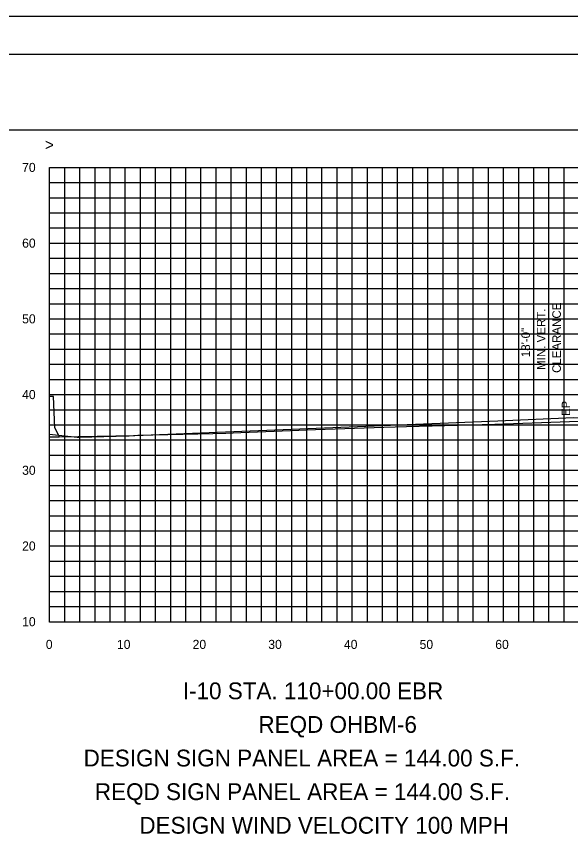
# Model space of a CAD drawing. Extents: x 1797809 to 2198143, y 249608 to 1237864.
# Drawn here: x 2195038.5 to 2195111.7, y 1237228.8 to 1237338 of the extents above; entities that cross this region are included whole.
import ezdxf

# ---------------------------------------------------------------- set-up
doc = ezdxf.new("R2010")
doc.units = 0
for name, color, linetype in [('10', 7, 'Continuous'), ('31', 7, 'Continuous'), ('60', 7, 'Continuous'), ('Default', 7, 'Continuous'), ('DESIGN - SHEET - Light Grid', 7, 'Continuous'), ('DESIGN - TRAFFIC CONTROL PERMANENT - Signs', 7, 'Continuous'), ('GSCOLORFILL', 7, 'Continuous'), ('GSSHT', 7, 'Continuous'), ('Level 45', 7, 'Continuous'), ('Level 55', 7, 'Continuous')]:
    doc.layers.add(name, color=color, linetype=linetype)

msp = doc.modelspace()

# ---------------------------------------------------------------- linework, layer by layer
at = {"layer": '60'}
for p, q in [((2195042.86, 1237258.11), (2195042.86, 1237318.11)), ((2195042.86, 1237258.05), (2195042.86, 1237258.11)), ((2195042.86, 1237258.11), (2195172.86, 1237258.11)), ((2195052.86, 1237258.05), (2195052.86, 1237258.11)), ((2195062.86, 1237258.05), (2195062.86, 1237258.11)), ((2195072.86, 1237258.05), (2195072.86, 1237258.11)), ((2195082.86, 1237258.05), (2195082.86, 1237258.11)), ((2195092.86, 1237258.05), (2195092.86, 1237258.11)), ((2195102.86, 1237258.05), (2195102.86, 1237258.11))]:
    msp.add_line(p, q, dxfattribs=at)
at = {"layer": 'Default'}
msp.add_lwpolyline([(2195042.86, 1237282.53), (2195044.11, 1237282.53), (2195044.11, 1237282.62), (2195044.1, 1237282.7), (2195043.55, 1237283.7), (2195043.36, 1237287.84), (2195042.86, 1237287.84)], dxfattribs=at)
at = {"layer": 'DESIGN - SHEET - Light Grid'}
msp.add_lwpolyline([(2195042.86, 1237282.87), (2195046.5, 1237282.47), (2195046.86, 1237282.48), (2195053.25, 1237282.68), (2195053.36, 1237282.68), (2195054.5, 1237282.73), (2195064.44, 1237282.98), (2195066.15, 1237283.03), (2195068.13, 1237283.1), (2195078.02, 1237283.48), (2195087.04, 1237283.79), (2195090.02, 1237283.89), (2195093.43, 1237283.98), (2195101.72, 1237284.21), (2195111.57, 1237284.54), (2195113.5, 1237284.6)], dxfattribs=at)
at = {"layer": 'DESIGN - TRAFFIC CONTROL PERMANENT - Signs'}
msp.add_lwpolyline([(2195042.86, 1237282.53), (2195043.92, 1237282.53), (2195044.11, 1237282.53), (2195054.11, 1237282.71), (2195066.11, 1237283.19), (2195078.11, 1237283.68), (2195090.11, 1237284.17), (2195102.11, 1237284.66), (2195112.1, 1237285.07), (2195124.1, 1237284.72), (2195126.1, 1237284.66), (2195127.61, 1237284.6)], dxfattribs=at)
at = {"layer": 'GSCOLORFILL'}
msp.add_lwpolyline([(2194870.36, 1237123.04), (2195192.86, 1237123.04), (2195192.86, 1237333.04), (2194870.36, 1237333.04)], close=True, dxfattribs=at)
at = {"layer": 'GSSHT'}
for p, q in [((2195042.86, 1237318.11), (2195172.86, 1237318.11)), ((2195044.86, 1237258.11), (2195044.86, 1237318.11)), ((2195046.86, 1237258.11), (2195046.86, 1237318.11)), ((2195048.86, 1237258.11), (2195048.86, 1237318.11)), ((2195050.86, 1237258.11), (2195050.86, 1237318.11)), ((2195052.86, 1237258.11), (2195052.86, 1237318.11)), ((2195054.86, 1237258.11), (2195054.86, 1237318.11)), ((2195056.86, 1237258.11), (2195056.86, 1237318.11)), ((2195058.86, 1237258.11), (2195058.86, 1237318.11)), ((2195060.86, 1237258.11), (2195060.86, 1237318.11)), ((2195062.86, 1237258.11), (2195062.86, 1237318.11)), ((2195064.86, 1237258.11), (2195064.86, 1237318.11)), ((2195066.86, 1237258.11), (2195066.86, 1237318.11)), ((2195068.86, 1237258.11), (2195068.86, 1237318.11)), ((2195070.86, 1237258.11), (2195070.86, 1237318.11)), ((2195072.86, 1237258.11), (2195072.86, 1237318.11)), ((2195074.86, 1237258.11), (2195074.86, 1237318.11)), ((2195076.86, 1237258.11), (2195076.86, 1237318.11)), ((2195078.86, 1237258.11), (2195078.86, 1237318.11)), ((2195080.86, 1237258.11), (2195080.86, 1237318.11)), ((2195082.86, 1237258.11), (2195082.86, 1237318.11)), ((2195084.86, 1237258.11), (2195084.86, 1237318.11)), ((2195086.86, 1237258.11), (2195086.86, 1237318.11)), ((2195088.86, 1237258.11), (2195088.86, 1237318.11)), ((2195090.86, 1237258.11), (2195090.86, 1237318.11)), ((2195092.86, 1237258.11), (2195092.86, 1237318.11)), ((2195094.86, 1237258.11), (2195094.86, 1237318.11)), ((2195096.86, 1237258.11), (2195096.86, 1237318.11)), ((2195098.86, 1237258.11), (2195098.86, 1237318.11)), ((2195100.86, 1237258.11), (2195100.86, 1237318.11)), ((2195102.86, 1237258.11), (2195102.86, 1237318.11)), ((2195104.86, 1237258.11), (2195104.86, 1237318.11)), ((2195106.86, 1237258.11), (2195106.86, 1237318.11)), ((2195108.86, 1237258.11), (2195108.86, 1237318.11)), ((2195110.86, 1237258.11), (2195110.86, 1237318.11)), ((2195042.86, 1237316.11), (2195172.86, 1237316.11)), ((2195042.86, 1237314.11), (2195172.86, 1237314.11)), ((2195042.86, 1237312.11), (2195172.86, 1237312.11)), ((2195042.86, 1237310.11), (2195172.86, 1237310.11)), ((2195042.86, 1237308.11), (2195172.86, 1237308.11)), ((2195042.86, 1237306.11), (2195172.86, 1237306.11)), ((2195042.86, 1237304.11), (2195172.86, 1237304.11)), ((2195042.86, 1237302.11), (2195172.86, 1237302.11)), ((2195042.86, 1237300.11), (2195172.86, 1237300.11)), ((2195042.86, 1237298.11), (2195172.86, 1237298.11)), ((2195042.86, 1237296.11), (2195172.86, 1237296.11)), ((2195042.86, 1237294.11), (2195172.86, 1237294.11)), ((2195042.86, 1237292.11), (2195172.86, 1237292.11)), ((2195042.86, 1237290.11), (2195172.86, 1237290.11)), ((2195042.86, 1237288.11), (2195172.86, 1237288.11)), ((2195042.86, 1237286.11), (2195172.86, 1237286.11)), ((2195042.86, 1237284.11), (2195172.86, 1237284.11)), ((2195042.86, 1237282.11), (2195172.86, 1237282.11)), ((2195042.86, 1237280.11), (2195172.86, 1237280.11)), ((2195042.86, 1237278.11), (2195172.86, 1237278.11)), ((2195042.86, 1237276.11), (2195172.86, 1237276.11)), ((2195042.86, 1237274.11), (2195172.86, 1237274.11)), ((2195042.86, 1237272.11), (2195172.86, 1237272.11)), ((2195042.86, 1237270.11), (2195172.86, 1237270.11)), ((2195042.86, 1237268.11), (2195172.86, 1237268.11)), ((2195042.86, 1237266.11), (2195172.86, 1237266.11)), ((2195042.86, 1237264.11), (2195172.86, 1237264.11)), ((2195042.86, 1237262.11), (2195172.86, 1237262.11)), ((2195042.86, 1237260.11), (2195172.86, 1237260.11)), ((2195042.86, 1237258.11), (2195172.86, 1237258.11))]:
    msp.add_line(p, q, dxfattribs=at)
msp.add_lwpolyline([(2194857.86, 1237118.04), (2195197.86, 1237118.04), (2195197.86, 1237338.04), (2194857.86, 1237338.04)], close=True, dxfattribs=at)
at = {"layer": 'Level 45'}
msp.add_lwpolyline([(2194882.86, 1237133.05), (2195182.86, 1237133.05), (2195182.86, 1237323.05), (2194882.86, 1237323.05)], close=True, dxfattribs=at)

# ---------------------------------------------------------------- texts
at = {"layer": '10'}
for s, p in [('0', (2195042.36, 1237254.51)), ('10', (2195051.76, 1237254.51)), ('20', (2195061.76, 1237254.51)), ('30', (2195071.76, 1237254.51)), ('40', (2195081.76, 1237254.51)), ('50', (2195091.76, 1237254.51)), ('60', (2195101.76, 1237254.51))]:
    msp.add_text(s, height=1.2, dxfattribs=at).set_placement(p)
at = {"layer": '31'}
for s, p in [('70', (2195039.23, 1237317.51)), ('60', (2195039.23, 1237307.51)), ('50', (2195039.23, 1237297.51)), ('40', (2195039.23, 1237287.51)), ('30', (2195039.23, 1237277.51)), ('20', (2195039.23, 1237267.51)), ('10', (2195039.23, 1237257.51))]:
    msp.add_text(s, height=1.2, dxfattribs=at).set_placement(p)
at = {"layer": '60'}
msp.add_text('>', height=1.5, dxfattribs=at).set_placement((2195042.25, 1237320.36))
at = {"layer": 'Level 55'}
for s, height, p in [('CLEARANCE', 1.135, (2195110.43, 1237290.97)), ('MIN. VERT.', 1.135, (2195108.39, 1237291.37)), ('18\'-0"', 1.135, (2195106.35, 1237293.05)), ('EP', 1.11, (2195111.65, 1237285.3))]:
    msp.add_text(s, height=height, rotation=90, dxfattribs=at).set_placement(p)
for s, p in [('I-10 STA. 110+00.00 EBR', (2195060.46, 1237247.87)), ('REQD OHBM-6', (2195070.45, 1237243.43)), ('DESIGN SIGN PANEL AREA = 144.00 S.F.', (2195047.35, 1237238.99)), ('REQD SIGN PANEL AREA = 144.00 S.F.', (2195048.84, 1237234.55)), ('DESIGN WIND VELOCITY 100 MPH', (2195054.72, 1237230.11))]:
    msp.add_text(s, height=2.2209, dxfattribs=at).set_placement(p)

doc.saveas('drawing.dxf')
